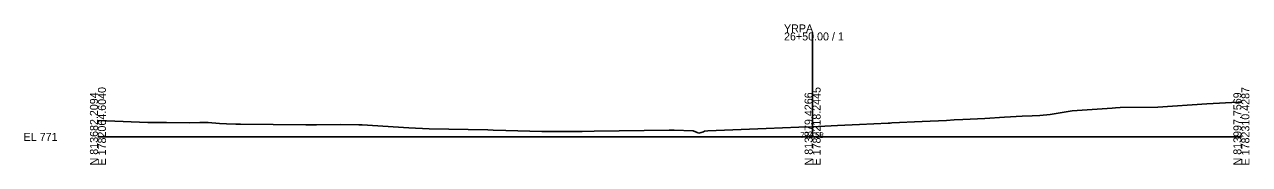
# Model space of a CAD drawing. Extents: x -26 to 2603, y -14 to 9545.
# Drawn here: x 874.3 to 1302.8, y 6990.3 to 7039.4 of the extents above; entities that cross this region are included whole.
import ezdxf

# ---------------------------------------------------------------- set-up
doc = ezdxf.new("R2010")
doc.units = 0
for name, color, linetype in [('Exist Cross Section Cell', 7, 'Continuous'), ('Exist XS Center Line Elevation Label', 7, 'Continuous'), ('Exist XS Ground Line', 7, 'Continuous')]:
    doc.layers.add(name, color=color, linetype=linetype)

msp = doc.modelspace()

# ---------------------------------------------------------------- linework, layer by layer
at = {"layer": 'Exist Cross Section Cell'}
for p, q in [((1150, 7000), (1150, 7036.62)), ((900, 7000), (1150, 7000)), ((1150, 7000), (1300, 7000))]:
    msp.add_line(p, q, dxfattribs=at)
at = {"layer": 'Exist XS Ground Line'}
for p, q in [((1270.73, 7010.44), (1287.97, 7011.61)), ((1287.97, 7011.61), (1298.87, 7012.21)), ((1298.87, 7012.21), (1300, 7012.21)), ((1210.27, 7006.48), (1217.1, 7006.9)), ((1217.1, 7006.9), (1223.32, 7007.21)), ((1223.32, 7007.21), (1226.77, 7007.44)), ((1226.77, 7007.44), (1229.47, 7007.53)), ((1229.47, 7007.53), (1233.09, 7007.85)), ((1233.09, 7007.85), (1240.76, 7009.08)), ((1240.76, 7009.08), (1254.85, 7010.12)), ((1254.85, 7010.12), (1255.97, 7010.23)), ((1255.97, 7010.23), (1257.54, 7010.31)), ((1257.54, 7010.31), (1270.73, 7010.44)), ((900, 7005.74), (903.01, 7005.68)), ((903.01, 7005.68), (917.51, 7005.07)), ((917.51, 7005.07), (923.93, 7005.1)), ((923.93, 7005.1), (932.06, 7004.9)), ((932.06, 7004.9), (935.62, 7005.1)), ((935.62, 7005.1), (938.57, 7005.03)), ((938.57, 7005.03), (942.56, 7004.71)), ((942.56, 7004.71), (945, 7004.58)), ((945, 7004.58), (948.22, 7004.41)), ((948.22, 7004.41), (949.89, 7004.42)), ((949.89, 7004.42), (972.75, 7004.23)), ((972.75, 7004.23), (976.47, 7004.28)), ((976.47, 7004.28), (984.82, 7004.32)), ((984.82, 7004.32), (991.29, 7004.27)), ((991.29, 7004.27), (992.44, 7004.27)), ((992.44, 7004.27), (1008.7, 7003.18)), ((1008.7, 7003.18), (1015.83, 7002.86)), ((1015.83, 7002.86), (1036.36, 7002.42)), ((1036.36, 7002.42), (1038.28, 7002.35)), ((1038.28, 7002.35), (1042.72, 7002.22)), ((1042.72, 7002.22), (1055.27, 7001.87)), ((1073.63, 7001.97), (1099.82, 7002.35)), ((1099.82, 7002.35), (1100.73, 7002.37)), ((1100.73, 7002.37), (1101.56, 7002.34)), ((1101.56, 7002.34), (1108.25, 7002.1)), ((1113.41, 7002.17), (1133.72, 7002.9)), ((1133.72, 7002.9), (1145.16, 7003.4)), ((1145.16, 7003.4), (1150, 7003.58)), ((1150, 7003.58), (1152.1, 7003.65)), ((1152.1, 7003.65), (1158.67, 7003.94)), ((1158.67, 7003.94), (1166.42, 7004.29)), ((1166.42, 7004.29), (1176.38, 7004.83)), ((1176.38, 7004.83), (1177.13, 7004.87)), ((1177.13, 7004.87), (1177.68, 7004.89)), ((1177.68, 7004.89), (1188.29, 7005.34)), ((1188.29, 7005.34), (1196.82, 7005.8)), ((1196.82, 7005.8), (1199.53, 7005.94)), ((1199.53, 7005.94), (1202.51, 7006.1)), ((1202.51, 7006.1), (1210.27, 7006.48)), ((1055.27, 7001.87), (1064, 7001.89)), ((1064, 7001.89), (1069.34, 7001.94)), ((1069.34, 7001.94), (1073.63, 7001.97)), ((1108.25, 7002.1), (1109.64, 7001.57)), ((1109.64, 7001.57), (1110.25, 7001.34)), ((1110.25, 7001.34), (1111.79, 7001.82)), ((1111.79, 7001.82), (1112.22, 7001.96)), ((1112.22, 7001.96), (1113.41, 7002.17))]:
    msp.add_line(p, q, dxfattribs=at)

# ---------------------------------------------------------------- texts
at = {"layer": 'Exist Cross Section Cell'}
for s, p in [('YRPA', (1140, 7036.62)), ('26+50.00 / 1', (1140, 7033.82)), ('EL 771', (874, 6998.6))]:
    msp.add_text(s, height=2.8, dxfattribs=at).set_placement(p)
for s, p in [('N 813682.2094', (900, 6990)), ('E 1782064.6040', (902.8, 6990)), ('N 813879.4266', (1150, 6990)), ('E 1782218.2445', (1152.8, 6990)), ('N 813997.7569', (1300, 6990)), ('E 1782310.4287', (1302.8, 6990))]:
    msp.add_text(s, height=2.8, rotation=90, dxfattribs=at).set_placement(p)
at = {"layer": 'Exist XS Center Line Elevation Label'}
msp.add_text('774.58', height=2, dxfattribs=at).set_placement((1145.73, 6999.58))

doc.saveas('drawing.dxf')
